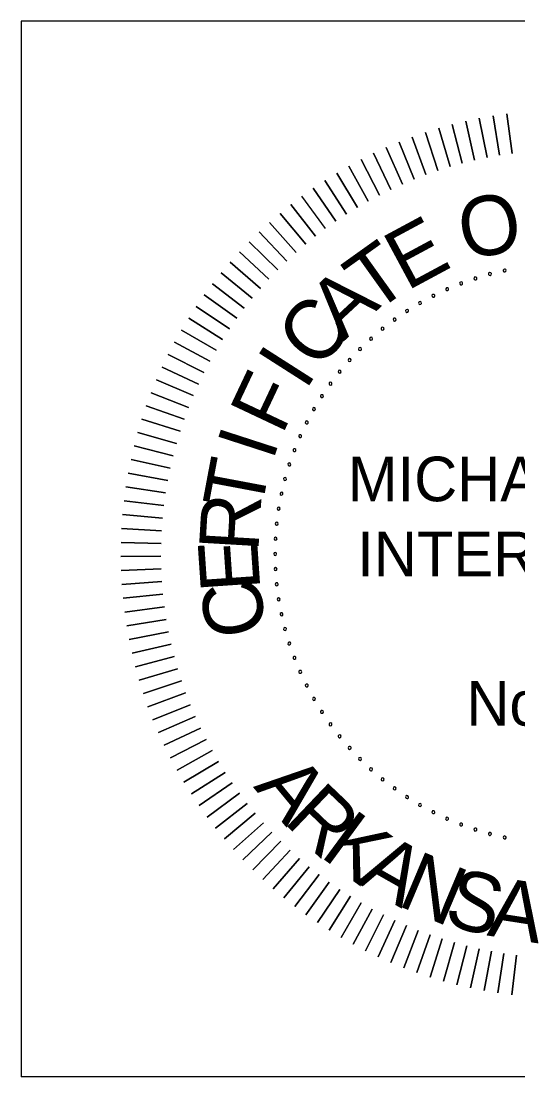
# Model space of a CAD drawing. Extents: x -549 to 3324, y -742 to 2142.
# Drawn here: x 2727.3 to 2866.5, y 78.3 to 374.1 of the extents above; entities that cross this region are included whole.
import ezdxf

# ---------------------------------------------------------------- set-up
doc = ezdxf.new("R2010")
doc.units = 0
doc.layers.add('G-ANNO-TEXT', color=7, linetype='Continuous')
doc.layers.add('R_No Plot', color=7, linetype='Continuous')

msp = doc.modelspace()

# ---------------------------------------------------------------- linework, layer by layer
at = {"layer": 'G-ANNO-TEXT'}
for points in [[(2857.87, 335.91), (2855.7, 346.92)], [(2855.7, 346.92), (2857.87, 335.91)], [(2861.37, 336.54), (2859.55, 347.62)], [(2859.55, 347.62), (2861.37, 336.54)], [(2864.88, 337.06), (2863.42, 348.19)], [(2863.42, 348.19), (2864.88, 337.06)], [(2847.51, 333.36), (2844.32, 344.12)], [(2844.32, 344.12), (2847.51, 333.36)], [(2850.93, 334.32), (2848.08, 345.18)], [(2848.08, 345.18), (2850.93, 334.32)], [(2854.39, 335.17), (2851.88, 346.11)], [(2851.88, 346.11), (2854.39, 335.17)], [(2837.44, 329.85), (2833.25, 340.26)], [(2833.25, 340.26), (2837.44, 329.85)], [(2840.76, 331.13), (2836.9, 341.67)], [(2836.9, 341.67), (2840.76, 331.13)], [(2844.11, 332.3), (2840.59, 342.95)], [(2840.59, 342.95), (2844.11, 332.3)], [(2834.16, 328.47), (2829.64, 338.75)], [(2829.64, 338.75), (2834.16, 328.47)], [(2827.74, 325.41), (2822.59, 335.38)], [(2822.59, 335.38), (2827.74, 325.41)], [(2830.92, 326.99), (2826.09, 337.12)], [(2826.09, 337.12), (2830.92, 326.99)], [(2821.53, 321.95), (2815.76, 331.58)], [(2815.76, 331.58), (2821.53, 321.95)], [(2824.6, 323.73), (2819.14, 333.53)], [(2819.14, 333.53), (2824.6, 323.73)], [(2818.5, 320.07), (2812.44, 329.51)], [(2812.44, 329.51), (2818.5, 320.07)], [(2815.54, 318.1), (2809.18, 327.35)], [(2809.18, 327.35), (2815.54, 318.1)], [(2809.81, 313.89), (2802.88, 322.72)], [(2802.88, 322.72), (2809.81, 313.89)], [(2812.64, 316.04), (2806, 325.08)], [(2807.05, 311.65), (2799.85, 320.26)], [(2799.85, 320.26), (2807.05, 311.65)], [(2804.36, 309.33), (2796.89, 317.7)], [(2796.89, 317.7), (2804.36, 309.33)], [(2801.74, 306.92), (2794.01, 315.06)], [(2794.01, 315.06), (2801.74, 306.92)], [(2799.2, 304.43), (2791.22, 312.32)], [(2791.22, 312.32), (2799.2, 304.43)], [(2796.74, 301.86), (2788.51, 309.5)], [(2788.51, 309.5), (2796.74, 301.86)], [(2794.36, 299.22), (2785.9, 306.59)], [(2785.9, 306.59), (2794.36, 299.22)], [(2792.06, 296.5), (2783.38, 303.6)], [(2783.38, 303.6), (2792.06, 296.5)], [(2789.85, 293.71), (2780.95, 300.54)], [(2780.95, 300.54), (2789.85, 293.71)], [(2787.73, 290.86), (2778.62, 297.4)], [(2778.62, 297.4), (2787.73, 290.86)], [(2785.71, 287.93), (2776.39, 294.19)], [(2776.39, 294.19), (2785.71, 287.93)], [(2783.77, 284.95), (2774.26, 290.91)], [(2774.26, 290.91), (2783.77, 284.95)], [(2781.93, 281.91), (2772.24, 287.57)], [(2772.24, 287.57), (2781.93, 281.91)], [(2780.18, 278.81), (2770.32, 284.16)], [(2770.32, 284.16), (2780.18, 278.81)], [(2778.54, 275.66), (2768.51, 280.69)], [(2768.51, 280.69), (2778.54, 275.66)], [(2776.99, 272.45), (2766.81, 277.17)], [(2766.81, 277.17), (2776.99, 272.45)], [(2775.54, 269.2), (2765.22, 273.6)], [(2765.22, 273.6), (2775.54, 269.2)], [(2774.2, 265.91), (2763.74, 269.98)], [(2763.74, 269.98), (2774.2, 265.91)], [(2772.96, 262.58), (2762.38, 266.32)], [(2762.38, 266.32), (2772.96, 262.58)], [(2771.83, 259.2), (2761.14, 262.61)], [(2761.14, 262.61), (2771.83, 259.2)], [(2770.8, 255.8), (2760.01, 258.87)], [(2760.01, 258.87), (2770.8, 255.8)], [(2769.88, 252.36), (2759, 255.09)], [(2759, 255.09), (2769.88, 252.36)], [(2769.07, 248.9), (2758.11, 251.29)], [(2758.11, 251.29), (2769.07, 248.9)], [(2768.37, 245.41), (2757.34, 247.45)], [(2757.34, 247.45), (2768.37, 245.41)], [(2767.78, 241.91), (2756.68, 243.6)], [(2756.68, 243.6), (2767.78, 241.91)], [(2767.3, 238.38), (2756.16, 239.73)], [(2756.16, 239.73), (2767.3, 238.38)], [(2766.93, 234.84), (2755.75, 235.84)], [(2755.75, 235.84), (2766.93, 234.84)], [(2766.67, 231.3), (2755.46, 231.94)], [(2755.46, 231.94), (2766.67, 231.3)], [(2766.52, 227.74), (2755.3, 228.03)], [(2755.3, 228.03), (2766.52, 227.74)], [(2766.48, 224.19), (2755.26, 224.12)], [(2755.26, 224.12), (2766.48, 224.19)], [(2766.56, 220.63), (2755.34, 220.22)], [(2755.34, 220.22), (2766.56, 220.63)], [(2766.75, 217.08), (2755.55, 216.31)], [(2755.55, 216.31), (2766.75, 217.08)], [(2767.05, 213.54), (2755.88, 212.42)], [(2755.88, 212.42), (2767.05, 213.54)], [(2767.46, 210), (2756.33, 208.53)], [(2756.33, 208.53), (2767.46, 210)], [(2767.98, 206.48), (2756.9, 204.67)], [(2756.9, 204.67), (2767.98, 206.48)], [(2768.61, 202.98), (2757.6, 200.82)], [(2757.6, 200.82), (2768.61, 202.98)], [(2769.35, 199.51), (2758.41, 197)], [(2758.41, 197), (2769.35, 199.51)], [(2770.2, 196.05), (2759.34, 193.2)], [(2759.34, 193.2), (2770.2, 196.05)], [(2771.15, 192.63), (2760.4, 189.44)], [(2760.4, 189.44), (2771.15, 192.63)], [(2772.22, 189.23), (2761.57, 185.71)], [(2761.57, 185.71), (2772.22, 189.23)], [(2773.39, 185.87), (2762.85, 182.01)], [(2762.85, 182.01), (2773.39, 185.87)], [(2774.67, 182.55), (2764.25, 178.36)], [(2764.25, 178.36), (2774.67, 182.55)], [(2776.05, 179.28), (2765.77, 174.76)], [(2765.77, 174.76), (2776.05, 179.28)], [(2777.53, 176.04), (2767.4, 171.21)], [(2767.4, 171.21), (2777.53, 176.04)], [(2779.11, 172.86), (2769.14, 167.71)], [(2769.14, 167.71), (2779.11, 172.86)], [(2780.79, 169.72), (2770.99, 164.26)], [(2770.99, 164.26), (2780.79, 169.72)], [(2782.57, 166.64), (2772.94, 160.88)], [(2772.94, 160.88), (2782.57, 166.64)], [(2784.45, 163.62), (2775, 157.56)], [(2775, 157.56), (2784.45, 163.62)], [(2786.42, 160.66), (2777.17, 154.3)], [(2777.17, 154.3), (2786.42, 160.66)], [(2788.48, 157.76), (2779.43, 151.11)], [(2779.43, 151.11), (2788.48, 157.76)], [(2790.63, 154.93), (2781.8, 148)], [(2781.8, 148), (2790.63, 154.93)], [(2792.87, 152.17), (2784.26, 144.96)], [(2784.26, 144.96), (2792.87, 152.17)], [(2795.19, 149.47), (2786.82, 142.01)], [(2786.82, 142.01), (2795.19, 149.47)], [(2797.6, 146.86), (2789.46, 139.13)], [(2789.46, 139.13), (2797.6, 146.86)], [(2800.09, 144.32), (2792.2, 136.34)], [(2792.2, 136.34), (2800.09, 144.32)], [(2802.66, 141.85), (2795.02, 133.63)], [(2795.02, 133.63), (2802.66, 141.85)], [(2797.93, 131.02), (2805.3, 139.48)], [(2805.3, 139.48), (2797.93, 131.02)], [(2800.91, 128.49), (2808.02, 137.18)], [(2808.02, 137.18), (2800.91, 128.49)], [(2803.98, 126.07), (2810.81, 134.97)], [(2810.81, 134.97), (2803.98, 126.07)], [(2807.12, 123.74), (2813.66, 132.85)], [(2813.66, 132.85), (2807.12, 123.74)], [(2810.33, 121.51), (2816.58, 130.82)], [(2816.58, 130.82), (2810.33, 121.51)], [(2813.61, 119.38), (2819.57, 128.89)], [(2819.57, 128.89), (2813.61, 119.38)], [(2816.95, 117.36), (2822.61, 127.05)], [(2822.61, 127.05), (2816.95, 117.36)], [(2820.36, 115.44), (2825.71, 125.3)], [(2825.71, 125.3), (2820.36, 115.44)], [(2823.82, 113.63), (2828.86, 123.66)], [(2828.86, 123.66), (2823.82, 113.63)], [(2827.34, 111.93), (2832.07, 122.11)], [(2832.07, 122.11), (2827.34, 111.93)], [(2830.92, 110.34), (2835.32, 120.66)], [(2835.32, 120.66), (2830.92, 110.34)], [(2834.54, 108.86), (2838.61, 119.32)], [(2838.61, 119.32), (2834.54, 108.86)], [(2838.2, 107.5), (2841.94, 118.08)], [(2841.94, 118.08), (2838.2, 107.5)], [(2841.91, 106.26), (2845.31, 116.95)], [(2845.31, 116.95), (2841.91, 106.26)], [(2845.65, 105.13), (2848.72, 115.92)], [(2848.72, 115.92), (2845.65, 105.13)], [(2849.43, 104.12), (2852.16, 115)], [(2852.16, 115), (2849.43, 104.12)], [(2853.23, 103.22), (2855.62, 114.19)], [(2855.62, 114.19), (2853.23, 103.22)], [(2857.06, 102.45), (2859.11, 113.49)], [(2859.11, 113.49), (2857.06, 102.45)], [(2860.92, 101.8), (2862.61, 112.9)], [(2862.61, 112.9), (2860.92, 101.8)], [(2864.79, 101.27), (2866.14, 112.42)], [(2866.14, 112.42), (2864.79, 101.27)]]:
    msp.add_lwpolyline(points, dxfattribs=at)
for centre, start, end in [((2854.6, 302.06), 18, 198), ((2854.6, 302.06), 198, 18), ((2858.68, 303.27), 15, 195), ((2858.68, 303.27), 195, 15), ((2862.81, 304.26), 12, 192), ((2862.81, 304.26), 192, 12), ((2846.67, 299.01), 24, 204), ((2846.67, 299.01), 204, 24), ((2850.6, 300.64), 21, 201), ((2850.6, 300.64), 201, 21), ((2842.83, 297.18), 27, 207), ((2842.83, 297.18), 207, 27), ((2835.47, 292.93), 33, 213), ((2835.47, 292.93), 213, 33), ((2839.09, 295.15), 30, 210), ((2839.09, 295.15), 210, 30), ((2831.96, 290.52), 36, 216), ((2831.96, 290.52), 216, 36), ((2828.59, 287.93), 39, 219), ((2828.59, 287.93), 219, 39), ((2825.36, 285.17), 42, 222), ((2825.36, 285.17), 222, 42), ((2822.27, 282.25), 45, 225), ((2822.27, 282.25), 225, 45), ((2819.35, 279.16), 48, 228), ((2819.35, 279.16), 228, 48), ((2816.58, 275.93), 51, 231), ((2816.58, 275.93), 231, 51), ((2814, 272.56), 54, 234), ((2814, 272.56), 234, 54), ((2811.59, 269.05), 57, 237), ((2811.59, 269.05), 237, 57), ((2809.37, 265.43), 60, 240), ((2809.37, 265.43), 240, 60), ((2807.34, 261.69), 63, 243), ((2807.34, 261.69), 243, 63), ((2805.51, 257.85), 66, 246), ((2805.51, 257.85), 246, 66), ((2803.88, 253.92), 69, 249), ((2803.88, 253.92), 249, 69), ((2802.46, 249.92), 72, 252), ((2802.46, 249.92), 252, 72), ((2801.25, 245.84), 75, 255), ((2801.25, 245.84), 255, 75), ((2800.26, 241.7), 78, 258), ((2800.26, 241.7), 258, 78), ((2799.49, 237.52), 81, 261), ((2799.49, 237.52), 261, 81), ((2798.93, 233.31), 84, 264), ((2798.93, 233.31), 264, 84), ((2798.6, 229.07), 87, 267), ((2798.6, 229.07), 267, 87), ((2798.49, 224.82), 90, 270), ((2798.49, 224.82), 270, 90), ((2798.6, 220.57), 93, 273), ((2798.6, 220.57), 273, 93), ((2798.93, 216.33), 96, 276), ((2798.93, 216.33), 276, 96), ((2799.49, 212.11), 99, 279), ((2799.49, 212.11), 279, 99), ((2800.26, 207.93), 102, 282), ((2800.26, 207.93), 282, 102), ((2801.25, 203.8), 105, 285), ((2801.25, 203.8), 285, 105), ((2802.46, 199.72), 108, 288), ((2802.46, 199.72), 288, 108), ((2803.88, 195.71), 111, 291), ((2803.88, 195.71), 291, 111), ((2805.51, 191.79), 114, 294), ((2805.51, 191.79), 294, 114), ((2807.34, 187.95), 117, 297), ((2807.34, 187.95), 297, 117), ((2809.37, 184.21), 120, 300), ((2809.37, 184.21), 300, 120), ((2811.59, 180.59), 123, 303), ((2811.59, 180.59), 303, 123), ((2814, 177.08), 126, 306), ((2814, 177.08), 306, 126), ((2816.58, 173.71), 129, 309), ((2816.58, 173.71), 309, 129), ((2819.35, 170.48), 132, 312), ((2819.35, 170.48), 312, 132), ((2822.27, 167.39), 135, 315), ((2822.27, 167.39), 315, 135), ((2825.36, 164.46), 138, 318), ((2825.36, 164.46), 318, 138), ((2828.59, 161.7), 141, 321), ((2828.59, 161.7), 321, 141), ((2831.96, 159.11), 144, 324), ((2831.96, 159.11), 324, 144), ((2835.47, 156.71), 147, 327), ((2835.47, 156.71), 327, 147), ((2839.09, 154.48), 150, 330), ((2839.09, 154.48), 330, 150), ((2842.83, 152.46), 153, 333), ((2842.83, 152.46), 333, 153), ((2846.67, 150.63), 336, 156), ((2846.67, 150.63), 156, 336), ((2850.6, 149), 159, 339), ((2850.6, 149), 339, 159), ((2854.6, 147.58), 342, 162), ((2854.6, 147.58), 162, 342), ((2858.68, 146.37), 165, 345), ((2858.68, 146.37), 345, 165), ((2862.81, 145.38), 168, 348), ((2862.81, 145.38), 348, 168)]:
    msp.add_arc(centre, 0.417, start, end, dxfattribs=at)
at = {"layer": 'R_No Plot'}
for p, q in [((2727.29, 374.15), (2727.29, 78.28)), ((3023.16, 374.15), (2727.29, 374.15)), ((3023.16, 78.28), (2727.29, 78.28))]:
    msp.add_line(p, q, dxfattribs=at)

# ---------------------------------------------------------------- texts
at = {"layer": 'G-ANNO-TEXT'}
for s, rotation, p in [('O', 10.7295, (2851.54, 307.14)), ('E', 28.279, (2835.36, 298.41)), ('T', 35.5725, (2826.05, 291.96)), ('A', 42.8659, (2817.59, 284.26)), ('C', 50.1594, (2810.58, 275.93)), ('I', 57.4529, (2806.95, 270.35)), ('F', 64.7464, (2800.41, 257.89)), ('I', 72.0398, (2797.83, 250.57)), ('T', 79.3333, (2794.52, 236.2)), ('R', 86.6268, (2793.75, 225.19)), ('E', 93.9203, (2794.37, 214.78)), ('C', 101.2137, (2796.5, 203.18)), ('A', 309.5859, (2792.23, 159.55)), ('R', 316.3356, (2800.51, 149.73)), ('K', 323.6428, (2810.71, 140.26)), ('A', 330.3925, (2821.12, 132.74)), ('N', 337.1422, (2832.35, 126.49)), ('S', 344.4494, (2845.24, 121.27)), ('A', 351.1991, (2857.65, 117.94))]:
    msp.add_text(s, height=16.67, rotation=rotation, dxfattribs=at).set_placement(p)
for s, height, p in [('MICHAEL BAKER', 12.5016, (2818.87, 239.59)), (' INTERNATIONAL', 12.5016, (2816.86, 218.57)), (' No. 1126', 12.502, (2847.43, 176.72))]:
    msp.add_text(s, height=height, dxfattribs=at).set_placement(p)

doc.saveas('drawing.dxf')
